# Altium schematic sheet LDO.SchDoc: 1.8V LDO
size 431 x 279 mm; Date: Not shown in title block; ApprovedBy: Not shown in title block; CheckedBy: Not shown in title block; Author: Not shown in title block; CompanyName: Not shown in title block; DrawnBy: T Zhou; Engineer: Not shown in title block; Organization: Not shown in title block; Address1: Not shown in title block; Address2: Not shown in title block; Address3: Not shown in title block; Address4: Not shown in title block; DocumentNumber: 3; Revision: Use project parameter SCH_Rev; SheetNumber: 3; SheetTotal: 4; PageSetup: Record=PageOptions¦CenterHorizontal=True¦CenterVertical=True¦PrintScale=1.00¦XCorrection=1.00¦YCorrection=1.00¦PrintKind=0¦BorderSize=5000000¦LeftOffset=0¦BottomOffset=0¦Orientation=2¦PaperLength=1000¦PaperWidth=1000¦Scale=100¦PaperSource=15¦PrintQuality=600¦MediaType=1¦DitherType=10¦PaperKind=Letter¦PrintScaleMode=1
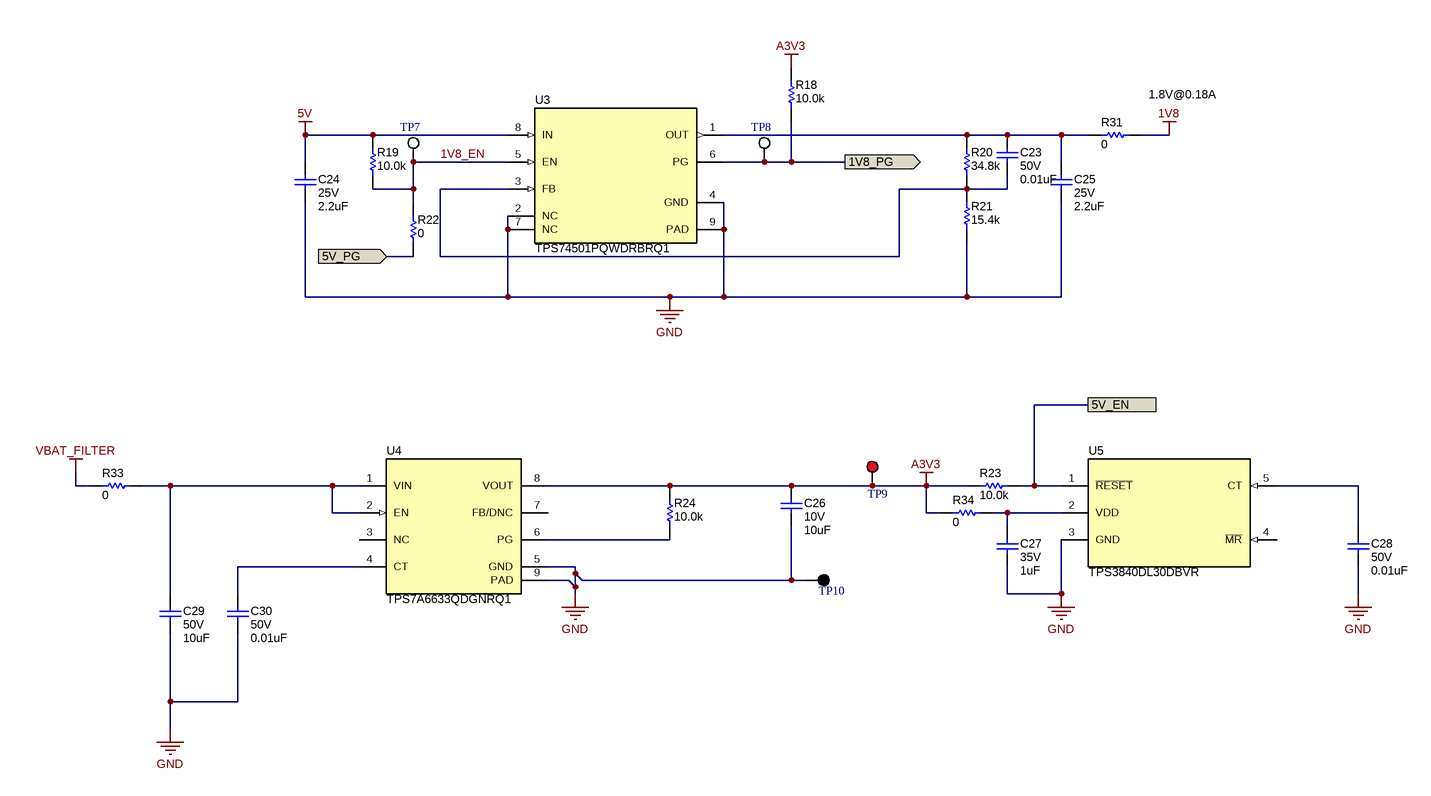
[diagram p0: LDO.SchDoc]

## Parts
C23  VDC_V: 50V  ValueDisplayed: 0.01uF  [0402S]  (hidden comment: GRM155R71H103KA88D)
C24  VDC_V: 25V  ValueDisplayed: 2.2uF  [0402S]  (hidden comment: C1005X5R1E225K050BC)
C25  VDC_V: 25V  ValueDisplayed: 2.2uF  [0402S]  (hidden comment: C1005X5R1E225K050BC)
C26  VDC_V: 10V  ValueDisplayed: 10uF  [1206]  (hidden comment: C3216X7R1A106M160AC)
C27  VDC_V: 35V  ValueDisplayed: 1uF  [0402S]  (hidden comment: GRM155R6YA105ME11D)
C28  VDC_V: 50V  ValueDisplayed: 0.01uF  [0402S]  (hidden comment: GRM155R71H103KA88D)
C29  VDC_V: 50V  ValueDisplayed: 10uF  [1210_270]  (hidden comment: UMJ325KB7106KMHT)
C30  VDC_V: 50V  ValueDisplayed: 0.01uF  [0402S]  (hidden comment: GRM155R71H103KA88D)
R18  ValueDisplayed: 10.0k  [0402S]  (hidden comment: RMCF0402FT10K0)
R19  ValueDisplayed: 10.0k  [0402S]  (hidden comment: RMCF0402FT10K0)
R20  ValueDisplayed: 34.8k  [0402S]  (hidden comment: CRCW040234K8FKED)
R21  ValueDisplayed: 15.4k  [0402S]  (hidden comment: CRCW040215K4FKED)
R22  ValueDisplayed: 0  [0402S]  (hidden comment: CRCW04020000Z0ED)
R23  ValueDisplayed: 10.0k  [0402S]  (hidden comment: RMCF0402FT10K0)
R24  ValueDisplayed: 10.0k  [0402S]  (hidden comment: RMCF0402FT10K0)
R31  ValueDisplayed: 0  [0603S]  (hidden comment: CRCW06030000Z0EA)
R33  ValueDisplayed: 0  [0402S]  (hidden comment: CRCW04020000Z0ED)
R34  ValueDisplayed: 0  [0402S]  (hidden comment: CRCW04020000Z0ED)
TP7  5002  [Keystone5002]  (value not drawn)
TP8  5002  [Keystone5002]  (value not drawn)
TP9  5000  [Keystone5000]  (value not drawn)
TP10  5001  [Keystone5001]  (value not drawn)
U3  TPS74501PQWDRBRQ1  [DRB0008J]
U4  TPS7A6633QDGNRQ1  [DGN0008D_N]
U5  TPS3840DL30DBVR  [DBV0005A_N]

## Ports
1V8_PG (out), 5V_EN, 5V_PG (in)

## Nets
1V8: R31.2
5V: C24.1 R19.2 U3.8(IN)
A3V3: C26.1 R18.2 R23.2 R24.2 R34.1 TP9.1 U4.8(VOUT)
GND: C24.2 C25.2 C26.2 C27.1 C28.1 C29.2 C30.1 R21.1 TP10.1 U3.2(NC) U3.4(GND) U3.7(NC) U3.9(PAD) U4.5(GND) U4.9(PAD) U5.3(GND)
VBAT_FILTER: R33.1
1V8_EN: R19.1 R22.1 TP7.1 U3.5(EN)
1V8_PG: R18.1 TP8.1 U3.6(PG) ; port 1V8_PG
5V_EN: R23.1 U5.1(~{RESET}) ; port 5V_EN
5V_PG: R22.2 ; port 5V_PG
NetC23_1: C23.1 C25.1 R20.2 R31.1 U3.1(OUT)
NetC23_2: C23.2 R20.1 R21.2 U3.3(FB)
NetC27_2: C27.2 R34.2 U5.2(VDD)
NetC28_2: C28.2 U5.5(CT)
NetC29_1: C29.1 R33.2 U4.1(VIN) U4.2(EN)
NetC30_2: C30.2 U4.4(CT)
NetR24_1: R24.1 U4.6(PG)

Not connected (* = marked no-connect by the designer): U4 3(NC) 7(FB/DNC); U5 4(~{MR})

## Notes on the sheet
- (near R31) 1.8V@0.18A

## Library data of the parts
C23 C28 C30 = CMP-0006674-2: CAP, CERM, 0.01 uF, 50 V, +/- 10%, X7R, 0402; Manufacturer: MuRata; TaMin_C: -55°C; Polarized: N; SizeAreaWB_mm2: 3; Value1: Unknown; U/M: EA; Value: 0.01uF; TaMax_C: 125°C; SizeZ_mm: 0.6; SizeX_mm: 1; SizeY_mm: 0.5; Cap_Case: 0402; Cap_F: 10nF; AEC Category: Q200
C24 C25 = CMP-0006278-2: CAP, CERM, 2.2 uF, 25 V, +/- 10%, X5R, 0402; Manufacturer: TDK; TaMin_C: -55°C; Polarized: N; SizeAreaWB_mm2: 3; Value1: Unknown; U/M: EA; Value: 2.2uF; TaMax_C: 85°C; SizeZ_mm: 0.6; SizeX_mm: 1; SizeY_mm: 0.5; Cap_Case: 0402; Cap_F: 2.2µF; AEC Category: Q200
C26 = CMP-0008689-2: CAP, CERM, 10 uF, 10 V, +/- 20%, X7R, 1206; Manufacturer: TDK; TaMin_C: -55°C; Polarized: N; SizeAreaWB_mm2: 10.92; Value1: 0.0046 ohm; U/M: EA; Value: 10uF; TaMax_C: 125°C; SizeZ_mm: 1.35; SizeX_mm: 3.2; SizeY_mm: 1.6; SizeArea_mm2: 5.12; Cap_F: 10µF; AEC Category: Q200; ESR_ohm: 4.6m
C27 = CMP-0006620-2: CAP, CERM, 1 uF, 35 V, +/- 20%, X5R, 0402; Manufacturer: MuRata; TaMin_C: -55°C; Polarized: N; SizeAreaWB_mm2: 3; Value1: Unknown; U/M: EA; Value: 1uF; TaMax_C: 85°C; SizeZ_mm: 0.6; SizeX_mm: 1; SizeY_mm: 0.5; Cap_Case: 0402; Cap_F: 1µF; AEC Category: Q200
C29 = CMP-0009257-2: CAP, CERM, 10 uF, 50 V, +/- 10%, X7R, AEC-Q200 Grade 1, 1210; Manufacturer: Taiyo Yuden; TaMin_C: -55°C; Polarized: N; SizeAreaWB_mm2: 14.7; Value1: Unknown; U/M: EA; Value: 10uF; TaMax_C: 125°C; SizeZ_mm: 2.7; SizeX_mm: 3.2; SizeY_mm: 2.5; Cap_Case: 1210; SizeArea_mm2: 8; AEC Qualified: Y; Cap_F: 10µF; AEC Grade: 1; AEC Category: Q200
R18 R19 R23 R24 = CMP-0026754-1: RES, 10.0 k, 1%, 0.063 W, AEC-Q200 Grade 0, 0402; Manufacturer: Stackpole Electronics Inc; Power_W: 63mW; TempCo: 100 ppm/C; Value_Code: 10k0; U/M: EA; Value: 10.0k; EIA_Code: E96; Res_ohm: 10k; SizeX_mm: 1; SizeY_mm: 0.5; SizeZ_mm: 0.6; Value2: 0.063W; AEC Qualified: Y; VDC_V: 50V; AEC Grade: 0; AEC Category: Q200
R20 = CMP-0026305-2: RES, 34.8 k, 1%, 0.063 W, AEC-Q200 Grade 0, 0402; Manufacturer: Vishay-Dale; Power_W: 63mW; TempCo: 100 ppm/C; Value_Code: 34k8; Value: 34.8k; EIA_Code: E96; SizeX_mm: 1; SizeY_mm: 0.5; SizeZ_mm: 0.6; Value2: 0.063W; AEC Qualified: Y; VDC_V: 50V; AEC Grade: 0; AEC Category: Q200
R21 = CMP-0026028-3: RES, 15.4 k, 1%, 0.063 W, AEC-Q200 Grade 0, 0402; Manufacturer: Vishay-Dale; Power_W: 63mW; TempCo: 100 ppm/C; Value_Code: 15k4; Value: 15.4k; EIA_Code: E96; SizeX_mm: 1; SizeY_mm: 0.5; SizeZ_mm: 0.6; Value2: 0.063W; AEC Qualified: Y; VDC_V: 50V; AEC Grade: 0; AEC Category: Q200
R22 R33 R34 = CMP-0026822-3: RES, 0, 5%, 0.063 W, AEC-Q200 Grade 0, 0402; Manufacturer: Vishay-Dale; Power_W: 63mW; TempCo: 200 ppm/C; Value_Code: 0000; Value: 0; EIA_Code: E24; SizeX_mm: 1; SizeY_mm: 0.5; SizeZ_mm: 0.6; Value2: 0.063W; AEC Qualified: Y; VDC_V: 50V; AEC Category: Q200
R31 = CMP-0025697-4: RES, 0, 5%, 0.1 W, AEC-Q200 Grade 0, 0603; Manufacturer: Vishay-Dale; Power_W: 100mW; TempCo: 200 ppm/C; Value_Code: 0000; Value: 0; EIA_Code: E24; SizeX_mm: 1.6; SizeY_mm: 0.8; SizeZ_mm: 1; Value2: 0.1W; SizeArea_mm2: 1.28; AEC Qualified: Y; VDC_V: 75V; AEC Category: Q200
TP7 TP8 = CMP-0055139-1: Test Point, Miniature, White, TH; Manufacturer: Keystone; CNHeader: FALSE; Green_Lifecycle: Active; Green_REACh: Passed; ContactFinish: Silver; CT: TRUE
TP9 = CMP-0055137-1: Test Point, Miniature, Red, TH; Manufacturer: Keystone; CNHeader: FALSE; Green_Lifecycle: Active; Green_REACh: Passed; ContactFinish: Silver; CT: TRUE
TP10 = CMP-0055138-1: Test Point, Miniature, Black, TH; Manufacturer: Keystone; CNHeader: FALSE; Green_Lifecycle: Active; Green_REACh: Passed; ContactFinish: Silver; CT: TRUE
U3 = CMP-0860764-1: 500-mA LDO With Power-Good in Small Wettable Flank WSON Package, DRB0008J (VSON-8); Manufacturer: Texas Instruments; SizeZ_mm: 1; SizeAreaWB_mm2: 16; CompType: IC; SizeArea_mm2: 9; SizeY_mm: 3; AEC Category: Q200; AEC Qualified: Y
U4 = CMP-0082577-1: High-Voltage Ultralow-I(q) Low-Dropout Regulator, DGN0008D (HVSSOP-8); Manufacturer: Texas Instruments; SizeZ_mm: 1.1; SizeAreaWB_mm2: 23.6; CompType: IC; SizeArea_mm2: 14.7; SizeY_mm: 3; SizeX_mm: 4.9; Rating: Automotive; AEC Qualified: Y; AEC Category: Q200
U5 = CMP-0084479-1: Nano Power, Wide VIN Voltage Detector with Programmable Delay, DBV0005A (SOT-23-5); Manufacturer: Texas Instruments; SizeZ_mm: 1.45; SizeArea_mm2: 8.12; SizeY_mm: 2.9; AEC Category: Q200; AEC Qualified: N; CompType: IC; SizeAreaWB_mm2: 14.82; SizeX_mm: 2.8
